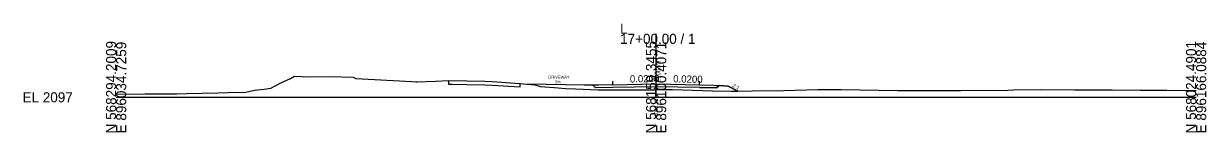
# Model space of a CAD drawing. Extents: x -26 to 1603, y -10 to 13527.
# Drawn here: x -25.7 to 302.8, y 4490.3 to 4520.4 of the extents above; entities that cross this region are included whole.
import ezdxf

# ---------------------------------------------------------------- set-up
doc = ezdxf.new("R2010")
doc.units = 0
for name, color, linetype in [('Default', 7, 'Continuous'), ('Exist XS Center Line Elevation Label', 7, 'Continuous'), ('Exist XS Ground Line', 7, 'Continuous'), ('Old_Level_61', 7, 'Continuous'), ('Old_Level_63', 7, 'Continuous'), ('Prop XS Ditch Standard Text', 7, 'Continuous'), ('Prop XS Earthwork Shape', 7, 'Continuous'), ('Prop XS EOT Tick Mark', 7, 'Continuous'), ('Prop XS Finish Grade', 7, 'Continuous'), ('Prop XS Finish Grade Earthwork', 7, 'Continuous'), ('Prop XS Finish Grade Paved Shoulder', 7, 'Continuous'), ('Prop XS Finish Grade Pavement', 7, 'Continuous'), ('Prop XS Side Slope Text', 7, 'Continuous'), ('Prop XS Subgrade Earthwork', 7, 'Continuous'), ('Prop XSC Text', 7, 'Continuous')]:
    doc.layers.add(name, color=color, linetype=linetype)

msp = doc.modelspace()

# ---------------------------------------------------------------- linework, layer by layer
at = {"layer": 'Exist XS Ground Line'}
for p, q in [((45.74, 4503.98), (48.43, 4505.19)), ((48.43, 4505.19), (49.52, 4505.87)), ((49.52, 4505.87), (53.83, 4505.7)), ((53.83, 4505.7), (59.45, 4505.79)), ((59.45, 4505.79), (65.8, 4505.56)), ((65.8, 4505.56), (66.58, 4505.24)), ((66.58, 4505.24), (82.11, 4504.38)), ((82.11, 4504.38), (83.23, 4504.32)), ((83.23, 4504.32), (83.59, 4504.33)), ((83.59, 4504.33), (88.69, 4504.52)), ((88.69, 4504.52), (92.35, 4504.65)), ((92.35, 4504.65), (97.38, 4504.57)), ((97.38, 4504.57), (102.39, 4504.49)), ((102.39, 4504.49), (104.42, 4504.36)), ((104.42, 4504.36), (112.19, 4503.87)), ((0, 4500.86), (8.06, 4500.98)), ((8.06, 4500.98), (15.94, 4501.01)), ((15.94, 4501.01), (16.86, 4501.01)), ((16.86, 4501.01), (19.54, 4501.06)), ((19.54, 4501.06), (28.21, 4501.2)), ((28.21, 4501.2), (31.03, 4501.3)), ((31.03, 4501.3), (36.06, 4501.47)), ((36.06, 4501.47), (38.41, 4501.98)), ((38.41, 4501.98), (41.13, 4502.27)), ((41.13, 4502.27), (42.97, 4502.53)), ((42.97, 4502.53), (45.74, 4503.98)), ((112.19, 4503.87), (113.16, 4503.78)), ((113.16, 4503.78), (116.27, 4503.44)), ((116.27, 4503.44), (117.79, 4503.04)), ((117.79, 4503.04), (121.64, 4502.7)), ((121.64, 4502.7), (124.88, 4502.47)), ((124.88, 4502.47), (127.62, 4502.33)), ((127.62, 4502.33), (133.91, 4502.07)), ((133.91, 4502.07), (136.18, 4502.07)), ((136.18, 4502.07), (148.77, 4502.11)), ((148.77, 4502.11), (149.5, 4502.12)), ((149.5, 4502.12), (150, 4502.13)), ((150, 4502.13), (152.83, 4502.18)), ((152.83, 4502.18), (154.51, 4502.14)), ((154.51, 4502.14), (165.7, 4501.77)), ((165.7, 4501.77), (170.87, 4501.7)), ((170.87, 4501.7), (176.68, 4501.8)), ((176.68, 4501.8), (185.45, 4501.93)), ((185.45, 4501.93), (194.88, 4502.19)), ((194.88, 4502.19), (201.38, 4502.13)), ((201.38, 4502.13), (217.16, 4501.85)), ((217.16, 4501.85), (223.85, 4501.89)), ((223.85, 4501.89), (234.61, 4501.91)), ((234.61, 4501.91), (247.67, 4501.99)), ((247.67, 4501.99), (249.34, 4502.03)), ((249.34, 4502.03), (256.64, 4502.16)), ((256.64, 4502.16), (266.21, 4502.1)), ((266.21, 4502.1), (270.67, 4502.07)), ((270.67, 4502.07), (276.71, 4502.04)), ((276.71, 4502.04), (284.46, 4502.01)), ((284.46, 4502.01), (291.86, 4501.97)), ((291.86, 4501.97), (297.07, 4501.9)), ((297.07, 4501.9), (298.88, 4501.9)), ((298.88, 4501.9), (300, 4501.89))]:
    msp.add_line(p, q, dxfattribs=at)
at = {"layer": 'Old_Level_61'}
for p, q in [((92.35, 4504.65), (92.35, 4503.65)), ((92.35, 4503.65), (93.35, 4503.63)), ((93.35, 4503.63), (97.38, 4503.57)), ((97.38, 4503.57), (102.39, 4503.49)), ((102.39, 4503.49), (104.42, 4503.36)), ((104.42, 4503.36), (112.19, 4502.87)), ((112.19, 4502.87), (112.19, 4503.87))]:
    msp.add_line(p, q, dxfattribs=at)
at = {"layer": 'Old_Level_63'}
for p, q in [((150, 4500), (150, 4517.6)), ((0, 4500), (150, 4500)), ((150, 4500), (300, 4500))]:
    msp.add_line(p, q, dxfattribs=at)
at = {"layer": 'Prop XS Earthwork Shape'}
msp.add_lwpolyline([(152.83, 4502.18), (154.51, 4502.14), (165.7, 4501.77), (170.87, 4501.7), (172.72, 4501.73), (170, 4503.09), (167.5, 4503.29), (166.81, 4502.6), (162, 4502.7), (150, 4502.94), (138, 4502.7), (133.19, 4502.6), (132.41, 4503.38), (130, 4503.33), (114.38, 4503.64), (116.27, 4503.44), (117.79, 4503.04), (121.64, 4502.7), (124.88, 4502.47), (127.62, 4502.33), (133.91, 4502.07), (136.18, 4502.07), (148.77, 4502.11), (149.5, 4502.12), (150, 4502.13)], close=True, dxfattribs=at)
at = {"layer": 'Prop XS EOT Tick Mark'}
for p, q in [((138, 4503.49), (138, 4504.49)), ((162, 4503.49), (162, 4504.49))]:
    msp.add_line(p, q, dxfattribs=at)
at = {"layer": 'Prop XS Finish Grade'}
for p, q in [((134, 4503.41), (132.41, 4503.38)), ((166, 4503.41), (167.5, 4503.29))]:
    msp.add_line(p, q, dxfattribs=at)
at = {"layer": 'Prop XS Finish Grade Earthwork'}
for p, q in [((130, 4503.33), (114.38, 4503.64)), ((132.41, 4503.38), (130, 4503.33)), ((167.5, 4503.29), (170, 4503.09)), ((170, 4503.09), (172.72, 4501.73))]:
    msp.add_line(p, q, dxfattribs=at)
at = {"layer": 'Prop XS Finish Grade Paved Shoulder'}
for p, q in [((138, 4503.49), (134, 4503.41)), ((162, 4503.49), (166, 4503.41))]:
    msp.add_line(p, q, dxfattribs=at)
at = {"layer": 'Prop XS Finish Grade Pavement'}
for p, q in [((138, 4503.49), (150, 4503.73)), ((150, 4503.73), (162, 4503.49))]:
    msp.add_line(p, q, dxfattribs=at)
at = {"layer": 'Prop XS Subgrade Earthwork'}
for p, q in [((133.19, 4502.6), (132.41, 4503.38)), ((138, 4502.7), (133.19, 4502.6)), ((150, 4502.94), (138, 4502.7)), ((162, 4502.7), (150, 4502.94)), ((162, 4502.7), (166.81, 4502.6)), ((166.81, 4502.6), (167.5, 4503.29))]:
    msp.add_line(p, q, dxfattribs=at)

# ---------------------------------------------------------------- texts
at = {"layer": 'Default'}
for rotation, p in [(1.1458, (142.72, 4504.08)), (358.8542, (154.72, 4504.14))]:
    msp.add_text('0.0200', height=2, rotation=rotation, dxfattribs=at).set_placement(p)
at = {"layer": 'Exist XS Center Line Elevation Label'}
msp.add_text('2099.13', height=1, rotation=90, dxfattribs=at).set_placement((150.5, 4494.6))
at = {"layer": 'Old_Level_63'}
for s, p in [('17+00.00 / 1', (140, 4514.8)), ('L', (140, 4517.6)), ('EL 2097', (-26, 4498.6))]:
    msp.add_text(s, height=2.8, dxfattribs=at).set_placement(p)
for s, p in [('N 568294.2009', (0, 4490)), ('E 896034.7259', (2.8, 4490)), ('N 568159.3455', (150, 4490)), ('E 896100.4071', (152.8, 4490)), ('N 568024.4901', (300, 4490)), ('E 896166.0884', (302.8, 4490))]:
    msp.add_text(s, height=2.8, rotation=90, dxfattribs=at).set_placement(p)
at = {"layer": 'Prop XS Ditch Standard Text'}
msp.add_text('DRIVEWAY', height=0.8, dxfattribs=at).set_placement((120.08, 4505.21))
msp.add_text('2%', height=0.8, rotation=358.8542, dxfattribs=at).set_placement((121.92, 4503.86))
at = {"layer": 'Prop XS Side Slope Text'}
msp.add_text('2:1', height=1, rotation=333.4349, dxfattribs=at).set_placement((171.08, 4502.93))
at = {"layer": 'Prop XSC Text'}
msp.add_text(' 2100.73', height=1.2, rotation=90, dxfattribs=at).set_placement((151.2, 4503.73))

doc.saveas('drawing.dxf')
